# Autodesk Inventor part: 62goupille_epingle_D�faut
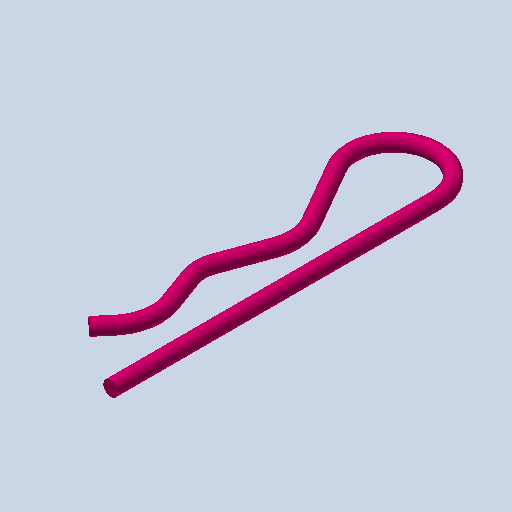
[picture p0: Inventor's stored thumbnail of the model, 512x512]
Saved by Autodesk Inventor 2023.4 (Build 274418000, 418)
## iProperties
Created: 2011-01
Part Number: 62goupille_epingle_D�faut
Document SubType Name: Modeling
Designer: eric
Density: 1 g/cm^3
Mass: 1.09547 g
Surface Area: 14.7477 cm^2
Volume: 1.09547 cm^3
Material: Générique
Appearance: 255,0,128_1
Author: eric
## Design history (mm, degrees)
feature "Base1"
node "Corps solides"
node "Corps surfaciques"
node "Solide1"
